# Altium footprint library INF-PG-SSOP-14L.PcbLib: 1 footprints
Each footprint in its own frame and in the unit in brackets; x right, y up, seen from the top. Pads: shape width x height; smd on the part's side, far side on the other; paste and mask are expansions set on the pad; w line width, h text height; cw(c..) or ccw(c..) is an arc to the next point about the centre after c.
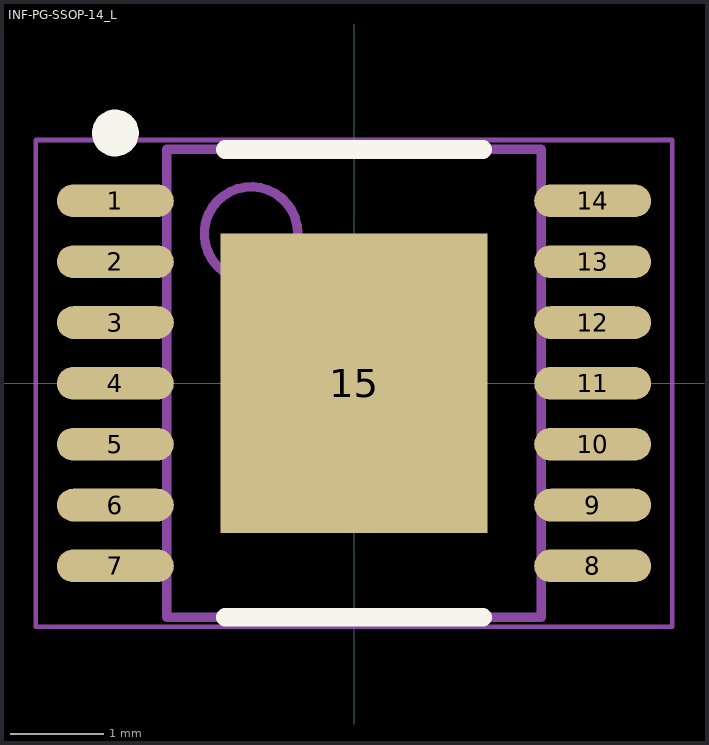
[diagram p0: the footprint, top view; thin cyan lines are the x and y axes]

## INF-PG-SSOP-14_L [mm] "SOP, 14-Leads, Body 4.9x3.9mm, Pitch 0.65mm, Thermal Pad 3.2x2.85mm, IPC High Density"
height 1.7
pads (15):
  oval 1.25x0.35 smd: 1(-2.55,1.95) 2(-2.55,1.3) 3(-2.55,0.65) 4(-2.55,0) 5(-2.55,-0.65) 6(-2.55,-1.3) 7(-2.55,-1.95) 8(2.55,-1.95) 9(2.55,-1.3) 10(2.55,-0.65) 11(2.55,0) 12(2.55,0.65) 13(2.55,1.3) 14(2.55,1.95)
  rect 2.85x3.2 smd: 15(0,0)
Top Overlay:
  circle w0.25: c-2.55,2.675 r0.125
  lines w0.2: -1.375,-2.5 1.375,-2.5 ; -1.375,2.5 1.375,2.5
Mechanical 13:
  circle w0.1: c-1.1,1.6 r0.5
  lines w0.1: -2,-2.5 -2,2.5 2,2.5 2,-2.5 -2,-2.5
Mechanical 15:
  lines w0.05: -3.4,-2.6 -3.4,2.6 3.4,2.6 3.4,-2.6 -3.4,-2.6
  lines w0.1: -0.5,0 0.5,0 ; 0,-0.5 0,0.5
3D body: height 1.7, standoff 0, extent -2,-2.5 2,2.5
